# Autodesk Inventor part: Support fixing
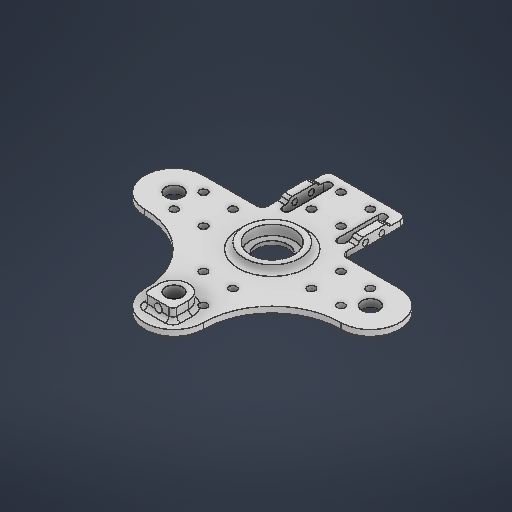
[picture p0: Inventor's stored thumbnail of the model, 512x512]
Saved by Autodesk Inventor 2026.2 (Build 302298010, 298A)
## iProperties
Created: 2026-04
Part Number: Support fixing
Material: 일반
Document SubType Name: Modeling
Designer: work
Density: 1 g/cm^3
Appearance: 기본값
Author: work
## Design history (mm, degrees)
sketch "스케치1"
  geometry: L1 (0, 0)-(50, 0); L2 (0, 0)-(0, 50); L3 (0, 0)-(-50, 0); L4 (0, 0)-(0, -50); L5 (-15, 50)-(15, 50); L6 (-50, -15)-(-50, 15); L7 (15, -50)-(-15, -50); L8 (50, 15)-(50, -15); L9 (50, -15)-(-50, -15); L10 (20, -15)-(-20, -15); L11 (-20, -15)-(-20, -48.5); L12 (-20, -48.5)-(20, -48.5); L13 (20, -48.5)-(20, -15); L14 (-7.5, 42.5)-(7.5, 42.5); L15 (7.5, 42.5)-(7.5, 27.5); L16 (7.5, 27.5)-(-7.5, 27.5); L17 (-7.5, 27.5)-(-7.5, 42.5); L18 (-7.5, 42.5)-(7.5, 27.5); L19 (7.5, 42.5)-(-7.5, 27.5); L20 (-27.5, 7.5)-(-27.5, -7.5); L21 (-27.5, -7.5)-(-42.5, -7.5); L22 (-42.5, -7.5)-(-42.5, 7.5); L23 (-42.5, -7.5)-(-27.5, 7.5); L24 (-42.5, 7.5)-(-27.5, -7.5); L25 (-42.5, 7.5)-(-27.5, 7.5); L26 (-7.5, -27.5)-(7.5, -27.5); L27 (7.5, -27.5)-(7.5, -42.5); L28 (7.5, -42.5)-(-7.5, -42.5); L29 (7.5, -42.5)-(-7.5, -27.5); L30 (-7.5, -42.5)-(7.5, -27.5); L31 (-7.5, -42.5)-(-7.5, -27.5); L32 (27.5, -7.5)-(27.5, 7.5); L33 (27.5, 7.5)-(42.5, 7.5); L34 (42.5, 7.5)-(42.5, -7.5); L35 (42.5, 7.5)-(27.5, -7.5); L36 (42.5, -7.5)-(27.5, 7.5); L37 (42.5, -7.5)-(27.5, -7.5); C1 r 8 at (0, 0); C2 r 11.2 at (0, 0); C3 r 4.4 at (50, 0); C4 r 4.4 at (0, 50); C5 r 4.4 at (-50, 0); C6 r 4.4 at (0, -50); C7 r 2 at (7.5, 42.5); C8 r 2 at (-7.5, 42.5); C9 r 2 at (-7.5, 27.5); C10 r 2 at (7.5, 27.5); C11 r 2 at (-27.5, -7.5); C12 r 2 at (-42.5, -7.5); C13 r 2 at (-27.5, 7.5); C14 r 2 at (-42.5, 7.5); C15 r 2 at (7.5, -27.5); C16 r 2 at (7.5, -42.5); C17 r 2 at (-7.5, -27.5); C18 r 2 at (-7.5, -42.5); C19 r 2 at (27.5, 7.5); C20 r 2 at (42.5, 7.5); C21 r 2 at (27.5, -7.5); C22 r 2 at (42.5, -7.5); A1 r 15 centre (0, 50) between (15, 50) and (-15, 50); A2 r 15 centre (-50, 0) between (-50, 15) and (-50, -15); A3 r 15 centre (0, -50) between (-15, -50) and (15, -50); A4 r 15 centre (50, 0) between (50, -15) and (50, 15); A5 r 35 centre (50, 50) between (15, 50) and (50, 15); A6 r 35 centre (-50, 50) between (-50, 15) and (-15, 50); 10 further points
  constraints: 74 end point, 28 centre point, 25 coincident, 12 point on circle, 5 horizontal, 5 midpoint, 4 parallel, 3 tangent, 2 perpendicular, 2 point on line, 1 concentric, 117 other
  dimensions: "d0" = 16 diameter of C1; "d1" = 22.4 diameter of C2; "d2" = 50 distance of L1.start L1.end; "d3" = 8.8 diameter of C3; "d6" = 360 deg dimension on L1.start L1.end (derived); "d8" = 30 distance of L5.start L5.end; "d11" = 360 deg dimension on L1.start A1.centre (derived); "d14" = 40 distance of L11.end L12.end; "d21" = 15 distance of L15.end L16.end; "d22" = 15 distance of L14.end L15.end; "d23" = 35 distance of C1.centre point (0, 35); "d24" = 4 diameter of C7; "d25" = 4 diameter of C8; "d26" = 4 diameter of C9; "d27" = 4 diameter of C10; "d30" = 360 deg dimension on L1.start L16.end (derived); "d32" = 6 distance between parallel lines of L12 L28
  node "스케치 - 원형 패턴1" dims "d6" = 360 deg (derived)
  node "스케치 - 원형 패턴2" dims "d11" = 360 deg (derived)
  node "스케치 - 원형 패턴4" dims "d30" = 360 deg (derived)
extrude "돌출1" new body sketch "스케치1" distance "d33" = 4; taper "d34" = 0 deg
extrude "돌출2" join sketch "스케치1" distance "d35" = 2; taper "d36" = 0 deg
sketch "스케치2"
  geometry: C1 r 14.2 at (0, 0); C2 r 11.2 at (0, 0) reference; 1 further point
  constraints: 1 centre point, 1 coincident, 1 concentric
  dimensions: "d37" = 3 radial gap between concentric circles of C1 C2
extrude "돌출3" join sketch "스케치2" distance "d38" = 3; taper "d39" = 0 deg
fillet "모깎기1" dims "d40" = 3
sketch "스케치3"
  geometry: L1 (20, 38.75)-(16, 38.75); L2 (16, 38.75)-(16, 24.75); L3 (16, 24.75)-(20, 24.75); L4 (20, 24.75)-(20, 38.75); L5 (20, 18)-(20, 45.5) reference; L6 (17, 48.5)-(-17, 48.5) reference; L7 (0, 48.5)-(0, 0); L8 (-20, 38.75)-(-16, 38.75); L9 (-16, 38.75)-(-16, 24.75); L10 (-16, 24.75)-(-20, 24.75); L11 (-20, 24.75)-(-20, 38.75); 1 further point
  constraints: 18 end point, 4 symmetric about line, 3 midpoint, 2 parallel, 1 horizontal, 1 perpendicular, 1 vertical
  dimensions: "d41" = 4 distance of L2.end L3.end; "d42" = 14 distance of L1.end L2.end
extrude "돌출4" join sketch "스케치3" distance "d43" = 2; taper "d44" = 0 deg
sketch "스케치4"
  geometry: L1 (20.75, 6)-(6.75, 6) reference; L2 (13.75, 6)-(13.75, 0); L3 (9.55, 3)-(17.95, 3); L4 (20.75, 4)-(6.75, 4) reference; L5 (9.55, 3)-(17.95, 3); L6 (0, 0)-(27.5, 0) reference; C1 r 1.5 at (9.55, 3); C2 r 1.5 at (17.95, 3); 2 further points
  constraints: 6 end point, 3 midpoint, 2 centre point, 2 coincident, 1 collinear, 1 horizontal, 1 parallel, 1 vertical
  dimensions: "d45" = 8.4 distance of L3.start L3.end; "d46" = 0 distance between parallel lines of L3 L5 (derived); "d47" = 3 diameter of C1; "d48" = 3 diameter of C2; "d49" = 3 distance between parallel lines of L6 L3
extrude "돌출5" cut sketch "스케치4" distance "d50" = 4; taper "d51" = 0 deg
sketch "스케치5"
  geometry: L1 (16, 19.25)-(12, 19.25); L2 (12, 19.25)-(12, 44.25); L3 (12, 44.25)-(16, 44.25); L4 (16, 44.25)-(16, 19.25); L5 (16, 38.75)-(16, 24.75) reference; 2 further points
  constraints: 8 end point, 2 midpoint, 2 parallel, 1 horizontal, 1 perpendicular
  dimensions: "d52" = 4 distance of L2.end L3.end; "d53" = 25 distance of L1.end L2.end
extrude "돌출6" cut sketch "스케치5" distance "d54" = 4; taper "d55" = 0 deg
fillet "모깎기2" dims "d56" = 2
node "작업 평면1"
fillet "모깎기3" dims "d57" = 2
chamfer "모따기1" distance "d58" = 1; stored, may be unused: second distance "d59" = 2, angle "d60" = 45 deg
sketch "스케치6"
  geometry: L1 (-16, 40.75)-(-20, 40.75) reference; L2 (-16, 40.75)-(-16, 42.25) reference; L3 (-12, 42.25)-(-12, 21.25) reference; L4 (-16, 21.25)-(-16, 22.75) reference; L5 (-20, 22.75)-(-16, 22.75) reference; L6 (-20, 22.75)-(-20, 18) reference; L7 (-23, 15)-(-50, 15) reference; L8 (50, 15)-(23, 15) reference; L9 (20, 18)-(20, 22.75) reference; L10 (16, 22.75)-(20, 22.75) reference; L11 (16, 22.75)-(16, 21.25) reference; L12 (12, 21.25)-(12, 42.25) reference; L13 (16, 42.25)-(16, 40.75) reference; L14 (20, 40.75)-(16, 40.75) reference; L15 (20, 40.75)-(20, 45.5) reference; L16 (17, 48.5)-(-17, 48.5) reference; L17 (-20, 45.5)-(-20, 40.75) reference; L18 (7.4, -50)-(-7.4, -50); L19 (-7.4, -50)-(-7.4, -58); L20 (-7.4, -58)-(7.4, -58); L21 (7.4, -58)-(7.4, -50); C1 r 4.4 at (-50, 0) reference; C2 r 4.4 at (0, -50) reference; C3 r 4.4 at (50, 0) reference; C4 r 2 at (-27.5, 7.5) reference; C5 r 2 at (-27.5, -7.5) reference; C6 r 2 at (27.5, -7.5) reference; C7 r 2 at (27.5, 7.5) reference; C8 r 2 at (7.5, -27.5) reference; C9 r 2 at (-7.5, -42.5) reference; C10 r 2 at (7.5, -42.5) reference; C11 r 2 at (-7.5, -27.5) reference; C12 r 2 at (42.5, 7.5) reference; C13 r 2 at (42.5, -7.5) reference; C14 r 2 at (-42.5, -7.5) reference; C15 r 2 at (-42.5, 7.5) reference; C16 r 2 at (7.5, 42.5) reference; C17 r 2 at (-7.5, 42.5) reference; C18 r 2 at (-7.5, 27.5) reference; C19 r 2 at (7.5, 27.5) reference; C20 r 17.2 at (0, 0) reference; A1 r 2 centre (-14, 42.25) between (-12, 42.25) and (-16, 42.25) reference; A2 r 2 centre (-14, 21.25) between (-16, 21.25) and (-12, 21.25) reference; A3 r 3 centre (-23, 18) between (-23, 15) and (-20, 18) reference; A4 r 15 centre (-50, 0) between (-50, 15) and (-50, -15) reference; A5 r 35 centre (-50, -50) between (-15, -50) and (-50, -15) reference; A6 r 15 centre (0, -50) between (-15, -50) and (15, -50) reference; A7 r 35 centre (50, -50) between (50, -15) and (15, -50) reference; A8 r 15 centre (50, 0) between (50, -15) and (50, 15) reference; A9 r 3 centre (23, 18) between (20, 18) and (23, 15) reference; A10 r 2 centre (14, 21.25) between (12, 21.25) and (16, 21.25) reference; A11 r 2 centre (14, 42.25) between (16, 42.25) and (12, 42.25) reference; A12 r 3 centre (17, 45.5) between (20, 45.5) and (17, 48.5) reference; A13 r 3 centre (-17, 45.5) between (-17, 48.5) and (-20, 45.5) reference; A14 r 7.4 centre (0, -50) between (7.4, -50) and (-7.4, -50); 1 further point
  constraints: 8 end point, 2 parallel, 2 point on circle, 1 centre point, 1 coincident, 1 horizontal, 1 perpendicular
  dimensions: "d61" = 3 radial gap between concentric circles of A14 C2; "d62" = 8 distance of L18.end L19.end; "d63" = 14.8 distance of L19.end L20.end
extrude "돌출7" join sketch "스케치6" distance "d64" = 6; taper "d65" = 0 deg
sketch "스케치7"
  geometry: L1 (-3.8, 3)-(18.6, 3) reference; L2 (14.8, 6)-(0, 6) reference; L3 (7.4, 6)-(7.4, -4); C1 r 2 at (7.4, 3)
  constraints: 2 end point, 2 midpoint, 1 centre point, 1 vertical
  dimensions: "d66" = 4 diameter of C1
extrude "돌출8" cut sketch "스케치7" stored distance "d67" = 6; taper "d68" = 0 deg
fillet "모깎기4" dims "d69" = 2
fillet "모깎기5" dims "d70" = 2
node "솔리드1"
mirror "미러1"
node "투영된 루프1"
